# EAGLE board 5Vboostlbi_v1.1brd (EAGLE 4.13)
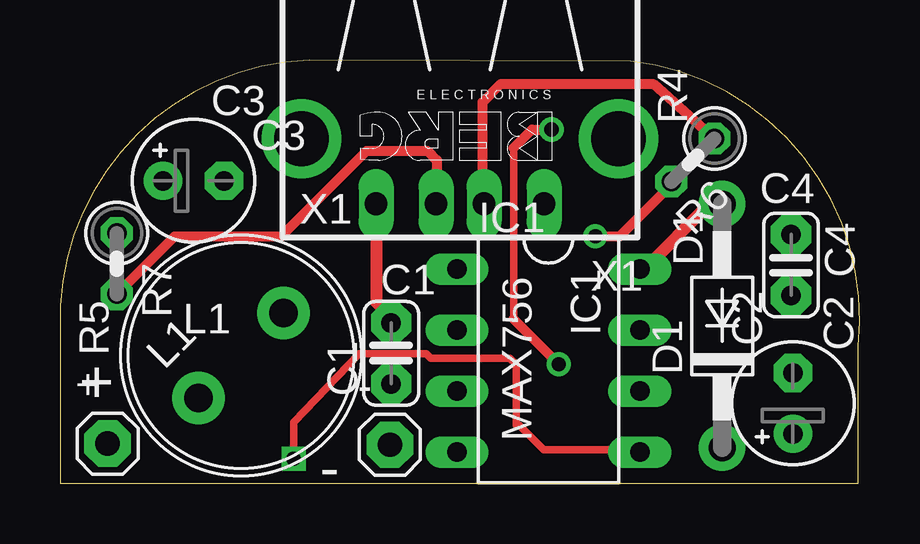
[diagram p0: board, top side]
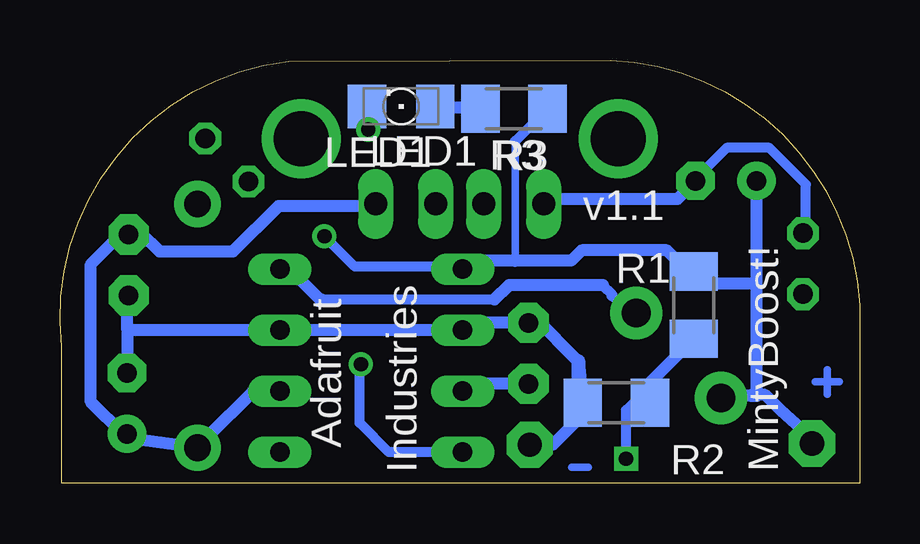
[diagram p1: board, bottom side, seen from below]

Size 33.32 x 17.63 mm. Coordinates in mm from the lower left corner, seen from the top.
Outline: 0,0 0,6.42 arc-90 10.38,17.63 23.79,17.58 arc-90 33.25,5.68 33.25,0
Outline: 0,0 33.25,0
Copper layers (1*16): Top 0.035mm / dielectric 1.5mm / Bottom 0.035mm
Design rules "default": minimum track width 12mil, minimum drill 23mil, track to track 10mil, track to pad 10mil, pad to pad 10mil, via to via 10mil, smd to smd 0mil, copper to edge 10mil, drill to drill 8mil, minimum pad ring 10mil, minimum via ring 8mil, stop-mask expansion 4mil, vias tented up to drill 0mil, thermal gap 10mil

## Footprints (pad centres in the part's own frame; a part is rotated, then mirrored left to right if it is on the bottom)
1X01 = drill 1.016 pad 1.93 octagon: 1 0,0
C025-024X044 = drill 0.813 pad 1.676 octagon: 1 -1.27,0; 2 1.27,0
E2,5-5 = drill 0.813 pad 1.6 round: + -1.27,0 | drill 0.813 pad 1.6 octagon: - 1.27,0
DO41-10 = drill 1.118 pad 1.93 round: A 5.08,0; C -5.08,0
DIL08 = drill 0.813 long: 1 -3.81,-3.81; 2 -1.27,-3.81; 3 1.27,-3.81; 4 3.81,-3.81; 5 3.81,3.81; 6 1.27,3.81; 7 -1.27,3.81; 8 -3.81,3.81
6000 = drill 1.2 pad 2.184 round: 1 -2.5,0; 2 2.5,0
1206 = smd 1.6 x 1.803: A -1.422,0; C 1.422,0
M1206 = smd 1.6 x 2: 1 -1.4,0; 2 1.4,0
0207/2V = drill 0.813 octagon: 1 -1.27,0; 2 1.27,0
PN87520 = drill 0.95 long: 1 -3.5,2.71; 2 -1,2.71; 3 1,2.71; 4 3.5,2.71 | drill 2.286 round: P$1 -6.604,0; P$2 6.604,0

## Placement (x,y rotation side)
+  [1X01]  1.99,1.65 0 top
-  [1X01]  13.75,1.6 0 top
C1  .1uF  [C025-024X044]  13.8,5.41 90 top
C2  100uF  [E2,5-5]  30.54,3.33 90 top
C3  100uF  [E2,5-5]  5.57,12.6 0 top
C4  .1uF  [C025-024X044]  30.46,9.1 270 top
D1  1N5817  [DO41-10]  27.59,6.56 90 top
IC1  MAX756  [DIL08]  20.35,5.11 270 top
L1  L  [6000]  7.54,5.32 45 top
LED1  RED  [1206]  19.11,15.7 180 bottom
R1  100K  [M1206]  6.91,7.42 270 bottom
R2  110K  [M1206]  10.14,3.36 180 bottom
R3  200-500ohm  [M1206]  14.41,15.6 180 bottom
R6  10K-50K  [0207/2V]  26.37,13.46 225 top
R7  10K-50K  [0207/2V]  2.37,9.15 270 top
X1  [PN87520]  16.67,14.35 180 top

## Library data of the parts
+ - = pinhead-ez
C1-C4 R6 R7 = rcl-ez
D1 IC1 L1 = usbbuck
LED1 = led
R1-R3 = rcl
X1 = con-berg

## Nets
D+: R7.2 X1.3
D-: R6.1 X1.2
GND: -.1 C1.2 C2.- C3.- C4.2 IC1.2 IC1.7 R2.2 R7.1 X1.4
N$1: C1.1 IC1.3
N$2: +.1 C3.+ IC1.1 L1.1 R1.1 R3.1 R6.2
N$5: D1.A IC1.8 L1.2
N$6: IC1.4 LED1.C
N$9: IC1.5 R1.2 R2.1
N$10: LED1.A R3.2
V+: C2.+ C4.1 D1.C IC1.6 X1.1

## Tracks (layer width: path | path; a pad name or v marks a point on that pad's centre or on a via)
D+
  Top 0.406: R7.2 4.78,10.29 9.22,10.29 12.78,13.85 15.32,13.85 15.7,13.46 15.7,11.68 X1.3
D-
  Top 0.406: R6.1 24.72,16.64 18.37,16.64 17.61,15.88 17.61,11.7 X1.2
GND
  Top 0.508: C1.2 13.92,6.79 13.17,7.54 X1.4
  Bottom 0.406: C3.- 6.84,12.68 5.54,13.97 3.76,13.97 2.24,12.45 2.24,10.29 R7.1
  Bottom 0.508: -.1 12.78,1.6 11.76,2.62 11.76,5.11 | 11.76,5.11 13.54,6.89 13.75,6.68 C1.2 16.13,6.68 16.44,6.38 IC1.2 IC1.7 30.51,6.38 | X1.4 12.97,11.84 7.6,11.84 C3.- | 30.54,4.8 C2.- 30.51,4.63 30.51,6.38 | C4.2 30.31,7.6 30.51,7.34 30.51,6.38 | 11.76,5.11 11.69,5.11 11.69,4.86 R2.2
N$1
  Bottom 0.508: IC1.3 16.41,3.84 16.34,3.76 15.96,4.14 C1.1
N$2  (via drill 0.6)
  Top 0.406: R6.2 25.47,12.46 25.48,12.45 23.32,10.29 v22.31,10.29
  Bottom 0.305: 14.36,9.27 14.36,14.25
  Bottom 0.406: 14.36,9.27 14.36,9.22 | 14.36,14.25 R3.1 | 16.67,8.84 16.84,9.02 21.04,9.02 v22.31,10.29
  Bottom 0.508: 4.3,8.31 4.3,3.63 4.53,3.63 | 4.3,8.31 C3.+ | +.1 1.99,1.86 3.29,3.03 3.94,3.69 4.53,3.69 4.53,3.63 | IC1.1 16.67,8.84 16.59,8.77 16.08,9.27 14.36,9.27 12.02,9.27 11.59,9.71 8.03,9.71 6.64,8.31 R1.1 6.53,8.31 4.3,8.31 | L1.1 6.18,3.43 6.18,3.63 4.53,3.63
N$4
  Bottom 0.305: 0.84,4.22 1.86,4.22
N$5
  Top 0.508: IC1.8 24.36,8.92 27.08,11.64 D1.A
  Bottom 0.406: 15.22,7.65 22.43,7.65 | L1.2 10.34,7.8 10.29,7.85 10.7,8.26
  Bottom 0.508: 24.29,8.94 IC1.8 23.75,8.92 22.48,7.65 22.43,7.65 | 15.22,7.65 14.61,8.26 10.7,8.26
N$6  (via drill 0.6)
  Top 0.305: 18.9,6.84 18.9,13.97
  Top 0.406: v20.78,4.96 18.9,6.84 | 18.9,13.97 19.66,14.73 v20.48,14.73
  Bottom 0.406: IC1.4 19.61,1.3 20.83,2.52 20.83,5.16 v20.78,4.96 | LED1.C 20.5,15.67 20.35,15.67 20.35,14.86 v20.48,14.73
N$7
  Bottom 0.305: 1.35,3.71 1.35,4.73
N$8
  Bottom 0.305: 11.99,0.66 11.31,0.66
N$9  (via drill 0.6)
  Top 0.305: IC1.5 24.19,1.4 20.15,1.4 19.13,2.42 19,2.42 19,4.96 18.75,5.21 15.45,5.21 15.27,5.39 12.48,5.39 9.73,2.54 v9.73,1.02
  Bottom 0.305: 9.7,2.42 9.73,2.42 9.73,1.15
  Bottom 0.406: v9.73,1.02 9.73,1.15 9.73,3.04 8.94,3.83
  Bottom 0.508: 8.94,3.83 R2.1 8.84,3.76 | 8.84,3.76 8.84,3.69 | R1.2 8.84,4.09 8.84,3.76
N$10
  Bottom 0.508: R3.2 15.86,15.65 17.63,15.65 LED1.A
V+
  Bottom 0.508: C2.+ 30.64,2.16 | C2.+ 30.33,1.86 D1.C 27.21,1.91 25.28,3.84 IC1.6 | X1.1 20.15,11.62 20.15,11.56 24.21,11.56 26.12,9.65 29.16,9.65 29.93,10.42 29.98,10.37 C4.1 30.79,10.37 32.03,9.12 32.03,3.38 30.69,2.03 30.66,2.06 C2.+

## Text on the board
tPlace: C3 | R4 | C4 | X1 | D1 | R5 | L1 | C1 | IC1 | C2 | + | MAX756 | -
bPlace: R3 | LED1 | v1.1 | R1 | R2 | Adafruit | MintyBoost! | Industries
